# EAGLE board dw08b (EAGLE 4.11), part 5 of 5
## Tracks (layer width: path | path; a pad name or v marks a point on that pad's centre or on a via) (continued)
P_MB07\  (via drill 0.61) (continued)
  Bottom 0.305: A15.H2 121.67,115.82 117.86,115.82 116.33,117.35 51.05,117.35 49.53,115.82 46.74,115.82 A21.H2 | v140.97,93.98 141.22,93.73 143.76,93.73 A13.R2
P_MB08  (via drill 0.61)
  Top 0.305: v50.8,96.52 50.55,96.27 50.55,95.25 50.8,95 50.8,91.95 50.55,91.69 50.55,88.9 50.8,88.65 50.8,85.6 50.55,85.34 50.55,82.55 50.8,82.3 v50.8,76.96 | v120.65,77.22 120.65,82.3 120.4,82.55 120.4,85.6 120.65,85.85 120.65,88.65 120.4,88.9 120.4,91.95 122.17,93.73 122.17,96.27 A15.P2 122.17,97.54 v122.17,100.84 | v131.83,107.95 131.83,112.01 A14.J2 | v127,107.7 127,104.65 126.75,104.39 v126.75,101.6
  Bottom 0.305: v50.8,96.52 49.02,96.52 48.77,96.77 46.74,96.77 A21.P2 | v50.8,76.96 56.13,76.96 56.39,77.22 69.34,77.22 69.6,76.96 71.88,76.96 72.39,77.47 79.76,77.47 80.01,77.22 92.96,77.22 93.22,76.96 94.23,76.96 94.74,77.47 100.84,77.47 101.09,77.22 v120.65,77.22 | v131.83,107.95 130.05,107.95 129.79,107.7 v127,107.7 | v126.75,101.6 124.21,101.6 123.7,101.09 122.43,101.09 v122.17,100.84
P_MB08\  (via drill 0.61)
  Top 0.305: v123.95,117.09 123.95,107.95 122.17,106.17 122.17,103.89 A15.M2
  Bottom 0.305: A15.M2 121.67,103.12 117.86,103.12 116.33,104.65 51.05,104.65 49.53,103.12 46.74,103.12 A21.M2 | v123.95,117.09 126.49,117.09 127,117.6 130.56,117.6 131.32,118.36 A14.F2
P_MB09  (via drill 0.61)
  Top 0.305: v129.79,92.2 129.79,94.74 130.3,95.25 130.3,100.33 130.56,100.58 130.56,100.84 130.81,101.09 130.81,105.66 131.06,105.92 A14.L2
  Bottom 0.305: A21.S2 46.74,90.42 49.53,90.42 51.05,91.95 116.33,91.95 117.86,90.42 121.67,90.42 A15.S2 122.68,91.19 126.24,91.19 127.25,92.2 v129.79,92.2
P_MB10  (via drill 0.61)
  Top 0.305: v123.95,98.04 124.21,97.79 124.21,94.23 123.95,93.98 123.95,93.22 124.21,92.96 124.21,87.88 v123.7,87.38
  Bottom 0.305: A21.T2 43.43,87.38 46.23,87.38 47.75,85.85 113.28,85.85 114.81,87.38 118.36,87.38 A15.T2 119.63,87.38 v123.7,87.38 | v123.95,98.04 126.49,98.04 127,98.55 130.56,98.55 131.32,99.31 A14.N2
P_MB11  (via drill 0.61)
  Top 0.305: v127,93.73 127,91.95 126.75,91.69 126.75,88.9 127,88.65 127,85.6 126.75,85.34 v126.75,82.8
  Bottom 0.305: A21.V2 43.43,81.03 47.24,81.03 48.51,82.3 113.28,82.3 114.55,81.03 118.36,81.03 A15.V2 119.63,81.03 122.17,81.03 123.95,82.8 v126.75,82.8 | v127,93.73 131.06,93.73 A14.R2
P_MBINCR  (via drill 0.61)
  Top 0.305: v17.53,82.55 17.53,86.61 A23.T2 | v20.07,82.3 19.81,82.04 19.81,78.49 20.07,78.23 v20.07,74.93 | v103.12,119.38 103.12,121.67 A17.E1 | v110.24,112.27 110.74,111.76 110.74,111.25 111.25,110.74 111.25,82.8 109.73,81.28 109.73,78.99 109.22,78.49 109.22,71.12 v109.47,70.87 | v104.9,65.53 104.9,63.5 104.39,62.99 v104.39,61.98 | v101.6,61.98 101.6,60.2 101.35,59.94 101.35,57.15 101.6,56.9 101.6,53.85 101.35,53.59 101.35,50.8 101.6,50.55 101.6,47.5 101.35,47.24 v101.35,45.72
  2 0.305: v86.36,40.89 86.36,40.39 88.9,37.85 88.9,37.59 89.92,36.58 92.46,36.58 92.96,36.07 B17.L2 95,37.85 97.28,37.85 98.55,39.12 98.55,39.88 98.04,40.39 98.04,43.18 99.82,44.96 v99.82,45.72 | v110.24,112.27 v103.12,119.38 | v105.66,70.87 105.66,69.34 105.16,68.83 105.16,65.79 v104.9,65.53
  15 0.305: v33.78,74.93 33.78,74.42 53.59,54.61 53.59,53.85 64.77,42.67 v64.77,41.66
  Bottom 0.305: v17.53,82.55 18.8,82.55 19.05,82.3 v20.07,82.3 | v20.07,74.93 v33.78,74.93 | v64.77,41.66 67.56,41.66 67.82,41.4 81.28,41.4 81.53,41.66 83.06,41.66 83.82,42.42 84.84,42.42 v86.36,40.89 | v109.47,70.87 109.22,70.61 105.92,70.61 v105.66,70.87 | v101.6,61.98 v104.39,61.98 | v99.82,45.72 v101.35,45.72
P_RUN  (via drill 0.61)
  Top 0.305: v34.54,77.72 34.54,82.04 35.05,82.55 35.05,85.34 34.54,85.85 34.54,89.66 34.04,90.17 A22.S2 | v49.53,77.72 v49.53,74.93 | v130.56,75.18 130.56,62.48 130.3,62.23 130.3,61.47 131.83,59.94 131.83,56.13 B14.D2 131.83,54.86 131.83,52.58 130.56,51.31 130.56,49.78 130.3,49.53 130.3,38.35 129.79,37.85 v129.79,35.05
  Bottom 0.305: v34.54,77.72 34.8,77.98 49.28,77.98 v49.53,77.72 | v49.53,74.93 52.32,74.93 52.83,75.44 56.64,75.44 56.9,75.69 68.83,75.69 69.09,75.44 72.39,75.44 72.9,75.95 79.25,75.95 79.5,75.69 92.46,75.69 92.71,75.44 94.74,75.44 95.25,75.95 100.33,75.95 100.58,75.69 119.63,75.69 119.89,75.44 130.3,75.44 v130.56,75.18 | v129.79,35.05 127.25,35.05 126.75,34.54 123.19,34.54 122.68,34.04 B15.M2
P_SKIP  (via drill 0.61)
  Top 0.305: v85.85,47.24 85.85,44.7 85.34,44.2 85.34,40.64 84.84,40.13 B18.K2 | v91.69,47.75 91.69,50.55 93.73,52.58 93.73,54.86 B17.D2 | v33.53,104.9 33.53,106.43 33.27,106.68 33.27,108.97 A22.K2 | v59.44,72.14 v59.44,79.76
  2 0.305: v33.53,104.9 39.88,98.55 40.64,98.55 v59.44,79.76 | v59.44,72.14 64.77,66.8 66.29,66.8 v85.85,47.24
  Bottom 0.305: v85.85,47.24 88.65,47.24 89.15,47.75 v91.69,47.75
P_TS1  (via drill 0.61)
  Top 0.305: v59.94,87.38 59.94,88.65 60.45,89.15 v60.45,90.17 | v63.5,90.17 63.25,90.42 63.25,91.95 63.5,92.2 63.5,95 63.25,95.25 63.25,98.3 63.5,98.55 v63.5,99.57 | v66.29,99.57 66.29,101.35 66.8,101.85 v66.8,103.63 | v70.87,105.66 71.37,106.17 71.37,108.97 A19.K2
  2 0.305: v68.58,103.63 68.83,103.63 v70.87,105.66
  Bottom 0.305: v59.94,87.38 56.13,87.38 A20.T2 | v60.45,90.17 v63.5,90.17 | v63.5,99.57 v66.29,99.57 | v66.8,103.63 v68.58,103.63
P_TS3  (via drill 0.61)
  Top 0.305: v57.15,124.71 57.15,123.95 56.9,123.7 56.9,120.65 57.15,120.4 57.15,117.6 56.9,117.35 56.9,114.3 57.15,114.05 57.15,111.25 56.9,111 56.9,107.95 57.15,107.7 57.15,104.9 56.9,104.65 56.9,101.6 57.15,101.35 57.15,98.55 56.9,98.3 56.9,95.25 58.67,93.47 58.67,91.19 A20.S2 | v66.8,119.89 68.33,121.41 68.33,124.71 A19.D2
  15 0.305: v59.18,124.71 v64.01,119.89
  Bottom 0.305: v57.15,124.71 v59.18,124.71 | v64.01,119.89 v66.8,119.89
P_TT_INST  (via drill 0.61)
  Top 0.305: v120.65,47.75 120.4,47.5 120.4,44.45 120.65,44.2 120.65,41.15 120.4,40.89 120.4,38.1 120.65,37.85 120.65,34.8 120.4,34.54 120.4,31.75 120.65,31.5 v120.65,29.97 v120.65,27.18 | v31.5,75.95 31.75,76.2 31.75,82.3 31.5,82.55 31.5,83.06 31.24,83.31 31.24,86.36 30.73,86.87 A22.T2 | v50.29,52.58 50.29,50.04 50.55,49.78 50.55,48.51 50.8,48.26 v50.8,47.75 | v85.85,32 85.85,29.72 86.11,29.46 86.11,26.92 v85.85,26.67
  2 0.305: v31.5,75.95 31.5,75.69 47.75,59.44 47.75,57.15 46.99,56.39 47.24,56.13 47.24,55.63 v50.29,52.58 | v70.1,47.75 71.88,47.75 85.85,33.78 v85.85,32 | v88.9,27.69 93.22,32 93.47,31.75 95,31.75 95.25,31.5 98.04,31.5 v100.33,33.78
  15 0.305: v100.33,33.78 102.87,36.32 103.12,36.07 103.89,36.07 105.41,34.54 v106.43,34.54 | v109.73,35.05 113.03,31.75 114.05,31.75 114.3,31.5 116.08,31.5 117.09,32.51 118.62,32.51 120.65,30.48 v120.65,29.97
  Bottom 0.305: v120.65,47.75 120.9,48.01 124.71,48.01 124.97,47.75 125.73,47.75 125.98,48.01 130.81,48.01 131.32,48.51 B14.F2 | v120.65,27.18 120.65,26.92 121.67,26.92 B15.P2 | v50.8,47.75 v70.1,47.75 | v85.85,26.67 86.87,27.69 v88.9,27.69 | v106.43,34.54 107.7,34.54 108.2,35.05 v109.73,35.05
P_WCOV  (via drill 0.61)
  Top 0.305: v120.65,25.4 120.65,22.35 120.4,22.1 120.4,19.05 120.65,18.8 120.65,16 119.13,14.48 119.13,11.68 B15.V2 119.13,10.41 v119.13,1.27 | v131.83,25.4 131.83,29.46 B14.N2 | v7.87,101.35 7.87,97.54 A24.P2 | v1.27,96.77 1.02,96.52 1.02,4.83 v1.27,4.57 | v32.51,4.57 v32.51,1.27
  Bottom 0.305: v120.65,25.4 120.9,25.15 123.7,25.15 123.95,25.4 126.75,25.4 127,25.15 130.05,25.15 130.3,25.4 v131.83,25.4 | v7.87,101.35 7.87,100.84 3.81,96.77 v1.27,96.77 | v1.27,4.57 v32.51,4.57 | v32.51,1.27 32.77,1.02 118.87,1.02 v119.13,1.27
VCC  (via drill 0.61)
  Top 1.27: v71.37,136.91 71.37,135.64 A19.A2 | v83.82,136.91 84.07,136.91 84.07,135.64 A18.A2 | v96.77,136.91 96.77,135.64 A17.A2 | v109.47,136.91 109.47,135.64 A16.A2 | v122.17,136.91 122.17,135.64 A15.A2 | v134.87,136.91 134.87,135.64 A14.A2 | v147.57,136.91 147.57,135.64 A13.A2 | v160.27,136.91 160.27,135.64 A12.A2 161.04,134.62 161.29,134.37 161.29,130.56 162.31,129.54 162.31,127 161.8,126.49 161.8,124.46 162.31,123.95 162.31,120.65 161.8,120.14 161.8,118.11 162.31,117.6 162.31,114.3 161.8,113.79 161.8,111.76 162.31,111.25 162.31,107.95 161.8,107.44 161.8,105.41 162.31,104.9 162.31,101.6 161.8,101.09 161.8,99.06 162.31,98.55 162.31,95.25 161.8,94.74 161.8,92.71 162.31,92.2 162.31,88.9 161.8,88.39 161.8,86.36 162.31,85.85 162.31,82.55 160.78,81.03 160.78,67.31 v160.27,67.06 160.27,65.79 B12.A2 | v45.97,67.06 45.97,65.79 B21.A2 | v58.42,67.06 58.67,67.06 58.67,65.79 B20.A2 | v71.37,67.06 71.37,65.79 B19.A2 | v84.07,67.06 84.07,65.79 B18.A2 | v96.77,67.06 96.77,65.79 B17.A2 | v109.47,67.06 109.47,65.79 B16.A2 | v122.17,67.06 122.17,65.79 B15.A2 | v134.87,67.06 134.87,65.79 B14.A2 | v147.57,67.06 147.57,65.79 B13.A2
  Bottom 1.27: v71.37,136.91 v83.82,136.91 v96.77,136.91 v109.47,136.91 v122.17,136.91 v134.87,136.91 v147.57,136.91 v160.27,136.91 | v45.97,67.06 v58.42,67.06 v71.37,67.06 v84.07,67.06 v96.77,67.06 v109.47,67.06 v122.17,67.06 v134.87,67.06 v147.57,67.06 v160.27,67.06

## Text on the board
Bottom: VRS | DW08B | DW08B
